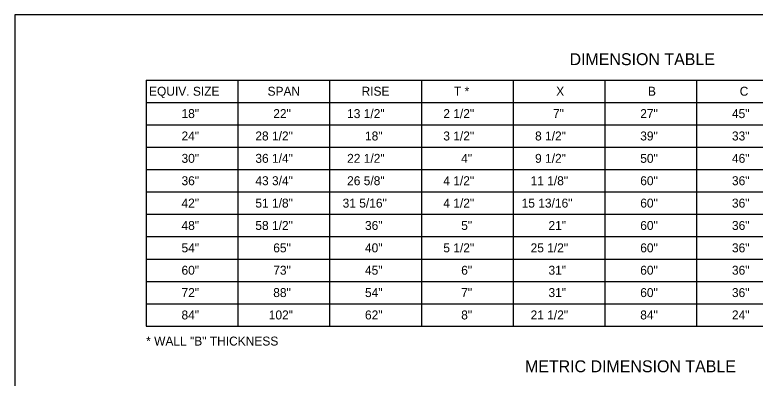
# Model space of a CAD drawing. Extents: x 49991.4 to 50021, y 49987.6 to 50011.4.
# Drawn here: x 50000.336 to 50005.302, y 50008.827 to 50011.263 of the extents above; entities that cross this region are included whole.
import ezdxf

# ---------------------------------------------------------------- set-up
doc = ezdxf.new("R2010")
doc.units = 0
doc.layers.add('Level 1', color=7, linetype='Continuous')
doc.layers.add('Level 2', color=7, linetype='Continuous')

msp = doc.modelspace()

# ---------------------------------------------------------------- linework, layer by layer
at = {"layer": 'Level 1'}
msp.add_lwpolyline([(50008.6146, 50011.2628), (50000.3356, 50011.2628), (50000.3356, 50000.0624), (50008.6146, 50000.0624)], close=True, dxfattribs=at)
at = {"layer": 'Level 2'}
for p, q in [((50001.2166, 50010.8254), (50007.9857, 50010.8254)), ((50001.2166, 50010.8254), (50001.2166, 50009.1754)), ((50001.8319, 50010.8254), (50001.8319, 50009.1754)), ((50001.8319, 50010.8254), (50001.8319, 50009.3254)), ((50002.4472, 50010.8254), (50002.4472, 50009.1754)), ((50003.0626, 50010.8254), (50003.0626, 50009.1754)), ((50003.678, 50010.8254), (50003.678, 50009.1754)), ((50004.2934, 50010.8254), (50004.2934, 50009.1754)), ((50004.9088, 50010.8254), (50004.9088, 50009.1754)), ((50001.2166, 50010.6754), (50007.9857, 50010.6754)), ((50001.2166, 50010.5254), (50007.9857, 50010.5254)), ((50001.2166, 50010.3754), (50007.9857, 50010.3754)), ((50001.2166, 50010.2254), (50007.9857, 50010.2254)), ((50001.2166, 50010.0754), (50007.9857, 50010.0754)), ((50001.2166, 50009.9254), (50007.9857, 50009.9254)), ((50001.2166, 50009.7754), (50007.9857, 50009.7754)), ((50001.2166, 50009.6254), (50007.9857, 50009.6254)), ((50001.2166, 50009.4754), (50007.9857, 50009.4754)), ((50001.2166, 50009.3254), (50007.9857, 50009.3254)), ((50001.2166, 50009.1754), (50007.9857, 50009.1754))]:
    msp.add_line(p, q, dxfattribs=at)

# ---------------------------------------------------------------- texts
for s, height, p in [('DIMENSION TABLE', 0.08, (50004.0566, 50010.9253)), ('EQUIV. SIZE', 0.06, (50001.2359, 50010.7204)), ('SPAN', 0.06, (50002.0309, 50010.7204)), ('RISE', 0.06, (50002.6614, 50010.7204)), ('T *', 0.06, (50003.2811, 50010.7204)), ('X', 0.06, (50003.9669, 50010.7204)), ('B', 0.06, (50004.5824, 50010.7204)), ('C', 0.06, (50005.1978, 50010.7204)), ('18"', 0.06, (50001.4538, 50010.5704)), ('22"', 0.06, (50002.0691, 50010.5704)), ('13 1/2"', 0.06, (50002.5644, 50010.5704)), ('2 1/2"', 0.06, (50003.2097, 50010.5704)), ('7"', 0.06, (50003.9452, 50010.5704)), ('27"', 0.06, (50004.5306, 50010.5704)), ('45"', 0.06, (50005.1458, 50010.5704)), ('24"', 0.06, (50001.4537, 50010.4204)), ('28 1/2"', 0.06, (50001.949, 50010.4204)), ('18"', 0.06, (50002.6845, 50010.4204)), ('3 1/2"', 0.06, (50003.2097, 50010.4204)), ('8 1/2"', 0.06, (50003.8253, 50010.4204)), ('39"', 0.06, (50004.5305, 50010.4204)), ('33"', 0.06, (50005.1458, 50010.4204)), ('30"', 0.06, (50001.4538, 50010.2704)), ('36 1/4"', 0.06, (50001.9491, 50010.2704)), ('22 1/2"', 0.06, (50002.5645, 50010.2704)), ('4"', 0.06, (50003.3297, 50010.2704)), ('9 1/2"', 0.06, (50003.8253, 50010.2704)), ('50"', 0.06, (50004.5307, 50010.2704)), ('46"', 0.06, (50005.1458, 50010.2704)), ('36"', 0.06, (50001.4538, 50010.1204)), ('43 3/4"', 0.06, (50001.9491, 50010.1204)), ('26 5/8"', 0.06, (50002.5644, 50010.1204)), ('4 1/2"', 0.06, (50003.2097, 50010.1204)), ('11 1/8"', 0.06, (50003.7952, 50010.1204)), ('60"', 0.06, (50004.5307, 50010.1204)), ('36"', 0.06, (50005.1458, 50010.1204)), ('42"', 0.06, (50001.4538, 50009.9704)), ('51 1/8"', 0.06, (50001.9491, 50009.9704)), ('31 5/16"', 0.06, (50002.5344, 50009.9704)), ('4 1/2"', 0.06, (50003.2098, 50009.9704)), ('15 13/16"', 0.06, (50003.7352, 50009.9704)), ('60"', 0.06, (50004.5307, 50009.9704)), ('36"', 0.06, (50005.1458, 50009.9704)), ('48"', 0.06, (50001.4537, 50009.8204)), ('58 1/2"', 0.06, (50001.949, 50009.8204)), ('36"', 0.06, (50002.6844, 50009.8204)), ('5"', 0.06, (50003.3298, 50009.8204)), ('21"', 0.06, (50003.9152, 50009.8204)), ('60"', 0.06, (50004.5307, 50009.8204)), ('36"', 0.06, (50005.1458, 50009.8204)), ('54"', 0.06, (50001.4538, 50009.6704)), ('65"', 0.06, (50002.0691, 50009.6704)), ('40"', 0.06, (50002.6844, 50009.6704)), ('5 1/2"', 0.06, (50003.2098, 50009.6704)), ('25 1/2"', 0.06, (50003.7953, 50009.6704)), ('60"', 0.06, (50004.5307, 50009.6704)), ('36"', 0.06, (50005.1458, 50009.6704)), ('60"', 0.06, (50001.4537, 50009.5204)), ('73"', 0.06, (50002.069, 50009.5204)), ('45"', 0.06, (50002.6844, 50009.5204)), ('6"', 0.06, (50003.3298, 50009.5204)), ('31"', 0.06, (50003.9152, 50009.5204)), ('60"', 0.06, (50004.5307, 50009.5204)), ('36"', 0.06, (50005.1458, 50009.5204)), ('72"', 0.06, (50001.4537, 50009.3704)), ('88"', 0.06, (50002.069, 50009.3704)), ('54"', 0.06, (50002.6845, 50009.3704)), ('7"', 0.06, (50003.3298, 50009.3704)), ('31"', 0.06, (50003.9152, 50009.3704)), ('60"', 0.06, (50004.5307, 50009.3704)), ('36"', 0.06, (50005.1457, 50009.3704)), ('84"', 0.06, (50001.4537, 50009.2204)), ('102"', 0.06, (50002.039, 50009.2204)), ('62"', 0.06, (50002.6845, 50009.2204)), ('8"', 0.06, (50003.3298, 50009.2204)), ('21 1/2"', 0.06, (50003.7952, 50009.2204)), ('84"', 0.06, (50004.5307, 50009.2204)), ('24"', 0.06, (50005.1457, 50009.2204)), ('* WALL "B" THICKNESS', 0.06, (50001.2166, 50009.0454)), ('METRIC DIMENSION TABLE', 0.08, (50003.7576, 50008.8662))]:
    msp.add_text(s, height=height, dxfattribs=at).set_placement(p)

doc.saveas('drawing.dxf')
